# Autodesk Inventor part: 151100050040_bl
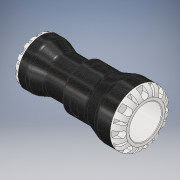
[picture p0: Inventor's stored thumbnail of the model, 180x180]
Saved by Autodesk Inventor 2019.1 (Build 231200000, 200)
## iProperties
Created: 2016-12
Part Number: 151100050040_bl
Material: PVC-Piping
Description: PLASSON G-PLASS  REDUCING COUPLING  50 x 40
Document SubType Name: Modeling
Designer: KIM
Mass: 309.689 g
Surface Area: 488.063 cm^2
Volume: 221.206 cm^3
Density: 1.4 g/cm^3
Appearance: Black Cast
Author: KIM
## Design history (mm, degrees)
derived "151100.ipt"
feature "Solid1::151100.ipt" dims "ScaleForDerivedMember" = 10
tag "TaggingFeature1"
body "Solid1"
other parameters: "E_" = 85 [user parameter], "H_" = 172 [user parameter], "l_" = 83 [user parameter], "l1" = 57 [user parameter], "Plasson" = 1 [user parameter], "d21" = 12.5 [user parameter], "d23" = 85 [user parameter], "d59" = 32.52113 [user parameter], "d0" = 172 [user parameter], "d2" = 34.86 [user parameter], "d4" = 85 [user parameter], "d6" = 83 [user parameter], "d7" = 4.16667 [user parameter], "d11" = 23.94 [user parameter], "d12" = 57 [user parameter], "d13" = 3.33333 [user parameter], "d14" = 68 [user parameter], "d15" = 56 [user parameter], "d16" = 20 deg [user parameter], "d17" = 20 deg [user parameter], "d18" = 130 deg [user parameter], "d26" = 0 [user parameter], "d28" = 360 deg [user parameter], "d30" = 8 deg [user parameter], "d31" = 1 [user parameter], "d32" = 8 deg [user parameter], "d33" = 1 [user parameter], "d35" = 0 [user parameter], "d37" = 360 deg [user parameter], "d39" = 8 [user parameter], "d42" = 8 [user parameter], "d43" = 0 [user parameter], "d45" = 360 deg [user parameter], "d47" = 0.8 [user parameter], "d48" = 8 deg [user parameter], "d49" = 8 deg [user parameter], "d50" = 0.8 [user parameter], "d52" = 0 [user parameter], "d54" = 360 deg [user parameter], "d56" = 14 [user parameter], "d57" = 17 [user parameter], "d58" = 0.5 [user parameter], "d60" = 10.2 [user parameter], "d61" = 12.5 [user parameter], "d62" = 16.2 [user parameter], "d63" = 0 [user parameter], "d66" = 0 [user parameter], "d68" = 360 deg [user parameter], "d75" = 16.26057 [user parameter], "d77" = 66.3 [user parameter], "d78" = 0.85 [user parameter]
